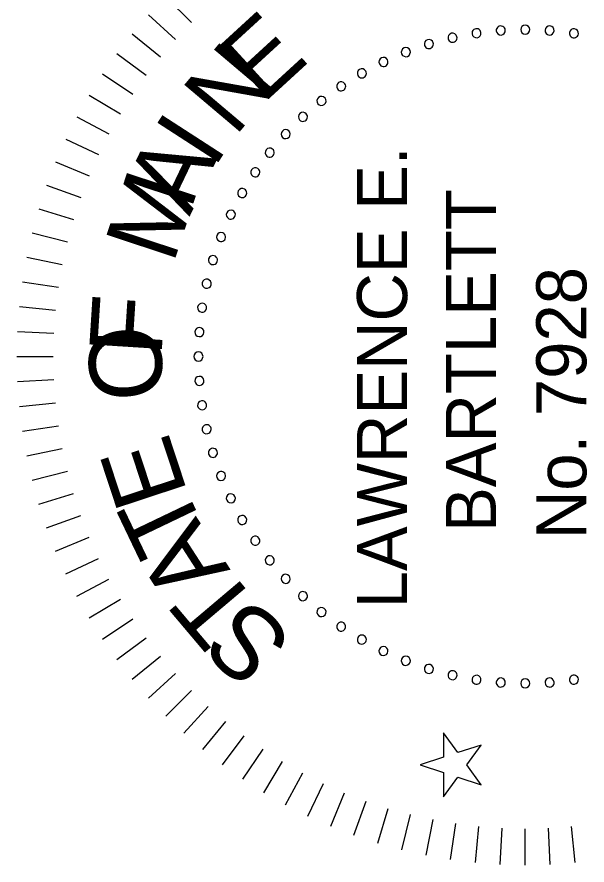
# Model space of a CAD drawing. Extents: x 916887 to 917745, y 329243 to 329793.
# Drawn here: x 917680.05 to 917702.39, y 329616.72 to 329649.92 of the extents above; entities that cross this region are included whole.
import ezdxf

# ---------------------------------------------------------------- set-up
doc = ezdxf.new("R2010")
doc.units = 0
doc.layers.add('Border', color=7, linetype='Continuous')
doc.layers.add('Default', color=7, linetype='Continuous')

# ---------------------------------------------------------------- blocks, each defined once
blk = doc.blocks.new('STAMP')
at = {"layer": 'Default'}
for p, q in [((-0.00039082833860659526, 0.009455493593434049), (-0.00036291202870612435, 0.008887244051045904)), ((-4.996003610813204e-18, 0.009465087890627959), (-4.996003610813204e-18, 0.008896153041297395)), ((0.0003908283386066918, 0.009455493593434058), (0.0003629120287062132, 0.008887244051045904)), ((-0.0015539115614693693, 0.009312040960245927), (-0.0014429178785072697, 0.00875403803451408)), ((-0.0011687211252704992, 0.009378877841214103), (-0.0010852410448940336, 0.008816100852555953)), ((-0.0007807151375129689, 0.009426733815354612), (-0.0007249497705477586, 0.00886053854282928)), ((0.0007807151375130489, 0.009426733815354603), (0.0007249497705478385, 0.00886053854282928)), ((0.0011687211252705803, 0.009378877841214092), (0.0010852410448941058, 0.008816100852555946)), ((0.001553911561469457, 0.009312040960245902), (0.001442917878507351, 0.008754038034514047)), ((-0.0019353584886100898, 0.009226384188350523), (-0.0017971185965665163, 0.008674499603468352)), ((0.0019353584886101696, 0.009226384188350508), (0.0017971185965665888, 0.008674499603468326)), ((-0.002312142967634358, 0.009122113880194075), (-0.002146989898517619, 0.008577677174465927)), ((0.0023121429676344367, 0.00912211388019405), (0.0021469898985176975, 0.008577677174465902)), ((-0.0026833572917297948, 0.008999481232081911), (-0.0024916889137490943, 0.00846380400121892)), ((0.002683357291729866, 0.008999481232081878), (0.0024916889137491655, 0.008463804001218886)), ((-0.003048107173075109, 0.008858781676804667), (-0.0028303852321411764, 0.008333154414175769)), ((0.00304810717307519, 0.008858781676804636), (0.002830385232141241, 0.008333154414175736)), ((-0.003405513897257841, 0.008700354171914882), (-0.0031622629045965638, 0.008186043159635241)), ((0.0034055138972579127, 0.008700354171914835), (0.0031622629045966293, 0.008186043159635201)), ((-0.0037547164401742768, 0.008524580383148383), (-0.0034865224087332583, 0.00802282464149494)), ((0.003754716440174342, 0.008524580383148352), (0.0034865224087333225, 0.008022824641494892)), ((-0.004094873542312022, 0.008331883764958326), (-0.003802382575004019, 0.0078438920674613)), ((0.0040948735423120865, 0.008331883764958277), (0.0038023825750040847, 0.007843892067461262)), ((-0.004425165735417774, 0.008122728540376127), (-0.004109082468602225, 0.0076496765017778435)), ((0.004425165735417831, 0.008122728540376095), (0.004109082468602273, 0.007649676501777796)), ((-0.004744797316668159, 0.007897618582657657), (-0.004405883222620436, 0.007440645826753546)), ((0.004744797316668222, 0.007897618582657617), (0.004405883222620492, 0.007440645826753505)), ((-0.0050529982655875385, 0.0076570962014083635), (-0.004692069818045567, 0.007217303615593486)), ((0.005052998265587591, 0.0076570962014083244), (0.004692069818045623, 0.0072173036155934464)), ((-0.005349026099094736, 0.007401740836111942), (-0.004966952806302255, 0.006980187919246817)), ((0.0053490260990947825, 0.0074017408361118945), (0.004966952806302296, 0.00698018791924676)), ((-0.0056321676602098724, 0.00713216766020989), (-0.00522986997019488, 0.006729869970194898)), ((0.005632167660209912, 0.007132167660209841), (0.005229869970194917, 0.006729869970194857)), ((-0.005901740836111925, 0.006849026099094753), (-0.005480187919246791, 0.006466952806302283)), ((-0.006157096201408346, 0.006552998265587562), (-0.005717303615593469, 0.006192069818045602)), ((-0.00639761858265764, 0.006244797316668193), (-0.0059406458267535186, 0.0059058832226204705)), ((-0.006622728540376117, 0.0059251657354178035), (-0.006149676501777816, 0.005609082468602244)), ((-0.006831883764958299, 0.005594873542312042), (-0.0063438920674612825, 0.0053023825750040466)), ((-0.007024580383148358, 0.005254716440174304), (-0.006522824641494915, 0.004986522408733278)), ((-0.007200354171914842, 0.00490551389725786), (-0.006686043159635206, 0.004662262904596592)), ((-0.0073587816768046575, 0.004548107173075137), (-0.006833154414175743, 0.004330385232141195)), ((-0.007499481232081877, 0.004183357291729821), (-0.006963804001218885, 0.003991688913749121)), ((-0.007622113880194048, 0.0038121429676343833), (-0.007077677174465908, 0.003646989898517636)), ((-0.007726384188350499, 0.0034353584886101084), (-0.007174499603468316, 0.003297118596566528)), ((-0.006396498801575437, 0.0031478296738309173), (-0.006515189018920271, 0.0027825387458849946)), ((-0.006277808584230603, 0.0027825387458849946), (-0.006396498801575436, 0.0031478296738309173)), ((-0.0078120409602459, 0.0030539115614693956), (-0.007254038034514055, 0.0029429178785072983)), ((-0.007878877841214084, 0.002668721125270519), (-0.007316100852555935, 0.0025852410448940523)), ((-0.006515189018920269, 0.0027825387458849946), (-0.006899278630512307, 0.0027825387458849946)), ((-0.006899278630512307, 0.0027825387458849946), (-0.006588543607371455, 0.002556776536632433)), ((-0.005893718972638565, 0.0027825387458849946), (-0.006277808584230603, 0.0027825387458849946)), ((-0.006204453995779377, 0.002556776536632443), (-0.005893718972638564, 0.0027825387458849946)), ((-0.006588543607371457, 0.002556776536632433), (-0.00670723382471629, 0.0021914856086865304)), ((-0.006085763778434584, 0.0021914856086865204), (-0.006204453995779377, 0.002556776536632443)), ((-0.006707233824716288, 0.0021914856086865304), (-0.006396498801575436, 0.0024172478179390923)), ((-0.006396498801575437, 0.0024172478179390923), (-0.006085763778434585, 0.0021914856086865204)), ((-0.007926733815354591, 0.00228071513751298), (-0.007360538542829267, 0.0022249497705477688)), ((-0.007955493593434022, 0.0018908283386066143), (-0.007387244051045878, 0.0018629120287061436)), ((-0.007965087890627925, 0.0015000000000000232), (-0.0073961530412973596, 0.0015000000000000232)), ((-0.007955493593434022, 0.0011091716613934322), (-0.007387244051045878, 0.0011370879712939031)), ((-0.007926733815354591, 0.0007192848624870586), (-0.007360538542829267, 0.0007750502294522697))]:
    blk.add_line(p, q, dxfattribs=at)
blk.add_lwpolyline([(-0.006277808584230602, 0.0027825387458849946), (-0.006396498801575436, 0.0031478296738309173), (-0.006515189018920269, 0.0027825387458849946), (-0.006899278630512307, 0.0027825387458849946), (-0.006588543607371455, 0.002556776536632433), (-0.006707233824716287, 0.0021914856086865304), (-0.006396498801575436, 0.0024172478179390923), (-0.0060857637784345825, 0.0021914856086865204), (-0.006204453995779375, 0.002556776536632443), (-0.005893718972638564, 0.0027825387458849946)], close=True, dxfattribs=at)
for centre, radius, start, end in [((-0.0003826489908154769, 0.006606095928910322), 7.111685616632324e-05, 4.285714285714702, 184.2857142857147), ((-4.718447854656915e-18, 0.006620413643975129), 7.111685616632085e-05, 0, 180), ((0.0003826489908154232, 0.0066060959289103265), 7.111685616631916e-05, 355.7142857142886, 175.71428571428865), ((-0.001139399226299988, 0.006492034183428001), 7.111685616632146e-05, 12.857142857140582, 192.8571428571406), ((-0.0007631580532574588, 0.006563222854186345), 7.111685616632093e-05, 8.571428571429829, 188.57142857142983), ((-0.0007631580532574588, 0.006563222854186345), 7.111685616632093e-05, 188.57142857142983, 8.571428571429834), ((-0.0003826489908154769, 0.006606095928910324), 7.111685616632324e-05, 184.28571428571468, 4.2857142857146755), ((-4.718447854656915e-18, 0.006620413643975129), 7.111685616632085e-05, 180, 0), ((0.0003826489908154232, 0.0066060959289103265), 7.111685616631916e-05, 175.71428571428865, 355.7142857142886), ((0.0007631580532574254, 0.006563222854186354), 7.111685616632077e-05, 171.42857142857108, 351.4285714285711), ((0.0007631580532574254, 0.006563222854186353), 7.111685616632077e-05, 351.42857142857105, 171.42857142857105), ((0.0011393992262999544, 0.006492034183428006), 7.111685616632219e-05, 347.14285714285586, 167.1428571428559), ((-0.0015092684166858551, 0.006392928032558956), 7.111685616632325e-05, 17.142857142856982, 197.142857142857), ((-0.0015092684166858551, 0.006392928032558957), 7.111685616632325e-05, 197.14285714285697, 17.14285714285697), ((-0.001139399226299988, 0.006492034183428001), 7.111685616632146e-05, 192.85714285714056, 12.857142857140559), ((0.0011393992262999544, 0.006492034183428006), 7.111685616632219e-05, 167.1428571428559, 347.14285714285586), ((0.0015092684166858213, 0.006392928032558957), 7.111685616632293e-05, 162.85714285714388, 342.8571428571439), ((0.0015092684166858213, 0.006392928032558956), 7.111685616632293e-05, 342.85714285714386, 162.85714285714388), ((-0.0018706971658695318, 0.006266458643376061), 7.111685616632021e-05, 21.42857142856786, 201.42857142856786), ((-0.0018706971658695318, 0.006266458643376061), 7.111685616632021e-05, 201.42857142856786, 21.428571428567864), ((0.0018706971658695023, 0.006266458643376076), 7.111685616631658e-05, 158.571428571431, 338.571428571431), ((0.0018706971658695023, 0.006266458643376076), 7.111685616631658e-05, 338.571428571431, 158.571428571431), ((-0.0022216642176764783, 0.0061133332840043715), 7.111685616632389e-05, 25.714285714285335, 205.71428571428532), ((-0.0022216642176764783, 0.006113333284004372), 7.111685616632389e-05, 205.71428571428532, 25.714285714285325), ((0.002221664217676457, 0.006113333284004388), 7.11168561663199e-05, 154.2857142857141, 334.2857142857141), ((0.002221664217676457, 0.006113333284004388), 7.11168561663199e-05, 334.2857142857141, 154.2857142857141), ((-0.0025602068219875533, 0.005934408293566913), 7.111685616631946e-05, 30.000000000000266, 210.00000000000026), ((0.002560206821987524, 0.005934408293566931), 7.111685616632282e-05, 330.0000000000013, 150.0000000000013), ((-0.0025602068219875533, 0.005934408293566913), 7.111685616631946e-05, 210.00000000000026, 30.000000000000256), ((0.002560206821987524, 0.005934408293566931), 7.11168561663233e-05, 150.00000000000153, 330.00000000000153), ((-0.002884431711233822, 0.005730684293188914), 7.11168561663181e-05, 34.28571428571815, 214.28571428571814), ((-0.002884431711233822, 0.005730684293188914), 7.111685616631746e-05, 214.2857142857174, 34.285714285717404), ((0.0028844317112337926, 0.005730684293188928), 7.111685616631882e-05, 145.71428571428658, 325.7142857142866), ((0.0028844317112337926, 0.005730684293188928), 7.111685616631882e-05, 325.7142857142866, 145.71428571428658), ((-0.003192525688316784, 0.0055033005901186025), 7.11168561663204e-05, 38.57142857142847, 218.57142857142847), ((-0.003192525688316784, 0.0055033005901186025), 7.111685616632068e-05, 218.57142857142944, 38.571428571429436), ((0.0031925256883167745, 0.00550330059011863), 7.111685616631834e-05, 141.42857142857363, 321.4285714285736), ((0.0031925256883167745, 0.00550330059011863), 7.111685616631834e-05, 321.4285714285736, 141.42857142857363), ((-0.0034827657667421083, 0.005253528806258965), 7.111685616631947e-05, 42.857142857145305, 222.8571428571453), ((0.003482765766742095, 0.005253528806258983), 7.111685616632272e-05, 317.1428571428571, 137.14285714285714), ((-0.0034827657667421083, 0.005253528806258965), 7.111685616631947e-05, 222.8571428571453, 42.857142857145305), ((0.003482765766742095, 0.005253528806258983), 7.111685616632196e-05, 137.1428571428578, 317.1428571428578), ((-0.0037535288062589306, 0.004982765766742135), 7.11168561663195e-05, 47.142857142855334, 227.14285714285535), ((0.0037535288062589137, 0.004982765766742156), 7.111685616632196e-05, 312.8571428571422, 132.8571428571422), ((-0.0037535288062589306, 0.004982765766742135), 7.11168561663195e-05, 227.14285714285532, 47.14285714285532), ((0.0037535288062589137, 0.004982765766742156), 7.111685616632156e-05, 132.85714285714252, 312.85714285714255), ((-0.004003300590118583, 0.004692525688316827), 7.111685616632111e-05, 51.428571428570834, 231.42857142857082), ((-0.004003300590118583, 0.004692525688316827), 7.111685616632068e-05, 231.42857142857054, 51.428571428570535), ((0.004003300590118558, 0.004692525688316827), 7.111685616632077e-05, 128.57142857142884, 308.57142857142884), ((0.004003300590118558, 0.004692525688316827), 7.111685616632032e-05, 308.5714285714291, 128.5714285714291), ((-0.0042306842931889, 0.004384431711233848), 7.11168561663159e-05, 55.71428571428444, 235.71428571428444), ((-0.0042306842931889, 0.004384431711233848), 7.111685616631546e-05, 235.7142857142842, 55.71428571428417), ((0.004230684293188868, 0.0043844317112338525), 7.111685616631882e-05, 124.28571428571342, 304.2857142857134), ((0.004230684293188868, 0.0043844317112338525), 7.111685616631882e-05, 304.2857142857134, 124.28571428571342), ((-0.004434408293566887, 0.004060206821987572), 7.111685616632e-05, 59.99999999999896, 239.99999999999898), ((-0.004434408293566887, 0.004060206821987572), 7.111685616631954e-05, 239.99999999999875, 59.999999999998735), ((0.004434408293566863, 0.004060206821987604), 7.111685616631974e-05, 120.00000000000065, 300.0000000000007), ((0.004434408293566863, 0.004060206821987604), 7.111685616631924e-05, 300.00000000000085, 120.00000000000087), ((-0.004613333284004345, 0.003721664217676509), 7.111685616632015e-05, 64.28571428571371, 244.2857142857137), ((-0.004613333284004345, 0.003721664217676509), 7.111685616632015e-05, 244.2857142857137, 64.2857142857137), ((0.004613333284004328, 0.0037216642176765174), 7.11168561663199e-05, 115.7142857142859, 295.7142857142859), ((0.004613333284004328, 0.0037216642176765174), 7.11168561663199e-05, 295.7142857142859, 115.71428571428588), ((-0.004766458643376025, 0.0033706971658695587), 7.111685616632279e-05, 68.57142857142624, 248.57142857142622), ((-0.004766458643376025, 0.0033706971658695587), 7.111685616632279e-05, 248.57142857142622, 68.57142857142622), ((0.004766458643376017, 0.0033706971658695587), 7.111685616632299e-05, 111.42857142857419, 291.4285714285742), ((0.004766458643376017, 0.0033706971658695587), 7.111685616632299e-05, 291.4285714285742, 111.42857142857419), ((-0.004892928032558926, 0.003009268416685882), 7.11168561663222e-05, 72.8571428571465, 252.8571428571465), ((-0.004892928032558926, 0.003009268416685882), 7.11168561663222e-05, 252.8571428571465, 72.8571428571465), ((0.004892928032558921, 0.003009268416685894), 7.111685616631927e-05, 107.14285714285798, 287.14285714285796), ((0.004892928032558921, 0.003009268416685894), 7.111685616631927e-05, 287.14285714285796, 107.14285714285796), ((-0.00499203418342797, 0.0026393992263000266), 7.111685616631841e-05, 77.14285714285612, 257.1428571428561), ((-0.004992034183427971, 0.0026393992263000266), 7.111685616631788e-05, 257.142857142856, 77.142857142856), ((0.004992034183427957, 0.002639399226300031), 7.111685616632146e-05, 102.85714285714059, 282.8571428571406), ((0.004992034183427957, 0.002639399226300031), 7.111685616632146e-05, 282.85714285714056, 102.85714285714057), ((-0.005063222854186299, 0.0022631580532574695), 7.111685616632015e-05, 81.42857142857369, 261.4285714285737), ((-0.005063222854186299, 0.0022631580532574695), 7.111685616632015e-05, 261.4285714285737, 81.42857142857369), ((0.005063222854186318, 0.0022631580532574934), 7.111685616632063e-05, 98.57142857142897, 278.57142857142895), ((0.005063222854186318, 0.0022631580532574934), 7.111685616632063e-05, 278.57142857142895, 98.57142857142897), ((-0.005106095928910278, 0.0018826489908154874), 7.111685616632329e-05, 85.7142857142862, 265.71428571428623), ((-0.005106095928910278, 0.0018826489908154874), 7.1116856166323e-05, 265.7142857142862, 85.71428571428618), ((0.005106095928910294, 0.0018826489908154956), 7.111685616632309e-05, 94.2857142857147, 274.2857142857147), ((0.005106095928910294, 0.0018826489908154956), 7.111685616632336e-05, 274.2857142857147, 94.28571428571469), ((-0.0051204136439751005, 0.0015000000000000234), 7.111685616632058e-05, 90, 270), ((-0.0051204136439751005, 0.0015000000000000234), 7.111685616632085e-05, 270, 90), ((0.005120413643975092, 0.0015000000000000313), 7.111685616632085e-05, 90, 270), ((0.005120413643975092, 0.0015000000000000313), 7.111685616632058e-05, 270, 90), ((-0.005106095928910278, 0.0011173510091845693), 7.111685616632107e-05, 94.28571428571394, 274.28571428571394), ((-0.005106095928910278, 0.0011173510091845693), 7.11168561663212e-05, 274.28571428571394, 94.28571428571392), ((0.005106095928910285, 0.0011173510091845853), 7.11168561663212e-05, 85.71428571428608, 265.71428571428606), ((0.005106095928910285, 0.0011173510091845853), 7.11168561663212e-05, 265.71428571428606, 85.71428571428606), ((-0.005063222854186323, 0.0007368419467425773), 7.111685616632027e-05, 98.5714285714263, 278.5714285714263), ((-0.005063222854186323, 0.0007368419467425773), 7.111685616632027e-05, 278.5714285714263, 98.5714285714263), ((0.005063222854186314, 0.0007368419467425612), 7.111685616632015e-05, 81.42857142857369, 261.4285714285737), ((0.005063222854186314, 0.0007368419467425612), 7.111685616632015e-05, 261.4285714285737, 81.42857142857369)]:
    blk.add_arc(centre, radius, start, end, dxfattribs=at)
for s, height, rotation, p in [('O', 0.0011378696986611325, 3.6537999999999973, (-0.0006627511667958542, 0.007158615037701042)), ('F', 0.0011378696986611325, 356.3462, (-7.4134925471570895e-06, 0.007201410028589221)), ('E', 0.0011378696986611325, 18.2692, (-0.0021355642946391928, 0.00678635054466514)), ('M', 0.001137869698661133, 341.7308, (0.0014314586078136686, 0.0070187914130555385)), ('T', 0.0011378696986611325, 25.576899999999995, (-0.0027590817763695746, 0.006486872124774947)), ('A', 0.0011378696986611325, 334.4231, (0.002184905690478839, 0.00676168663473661)), ('A', 0.0011378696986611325, 32.884600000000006, (-0.003341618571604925, 0.006114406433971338)), ('I', 0.0011378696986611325, 327.1154, (0.0029245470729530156, 0.00638406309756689)), ('T', 0.001137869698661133, 40.19230000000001, (-0.003928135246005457, 0.005629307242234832)), ('N', 0.001137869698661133, 319.8077, (0.003425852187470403, 0.0060536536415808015)), ('S', 0.001137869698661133, 47.49999999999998, (-0.004421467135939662, 0.00509611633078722)), ('E', 0.001137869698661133, 312.5, (0.0039441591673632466, 0.005617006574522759))]:
    blk.add_text(s, height=height, rotation=rotation, dxfattribs=at).set_placement(p)
for s, p in [('LAWRENCE E.', (-0.003944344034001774, 0.0033503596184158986)), ('BARTLETT', (-0.0027479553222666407, 0.001958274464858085)), ('No. 7928', (-0.002860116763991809, 0.0005420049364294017))]:
    blk.add_text(s, height=0.0007851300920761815, dxfattribs=at).set_placement(p)

msp = doc.modelspace()

# ---------------------------------------------------------------- block references
at = {"layer": 'Border', "xscale": 2499.999999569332, "yscale": 2499.999999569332, "rotation": 90}
msp.add_blockref('STAMP', (917703.7166483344, 329636.6288155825), dxfattribs=at)

doc.saveas('drawing.dxf')
